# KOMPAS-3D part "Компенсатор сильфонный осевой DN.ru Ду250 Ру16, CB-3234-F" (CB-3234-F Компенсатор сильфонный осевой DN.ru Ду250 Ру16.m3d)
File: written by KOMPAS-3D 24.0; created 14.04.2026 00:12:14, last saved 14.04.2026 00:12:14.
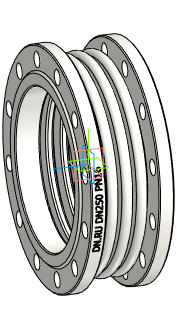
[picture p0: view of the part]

Document properties: Автор: DN.RU; Полное имя файла: D:\PROJECT CAD\DN.RU\...198(ACTUALE). CB-3234-F Компенсатор сильфонный осевой DN.ru\Исходники\DN250\CB-3234-F Компенсатор сильфонный осевой DN.ru Ду250 Ру16.m3d

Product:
- Body: Твердое тело1  | qty 1
    Масса: 34.981175
- Part/product: Компенсатор сильфонный осевой DN.ru Ду250 Ру16  | designation CB-3234-F
    Масса: 25.5
    Раздел спецификации: Прочие изделия
    Комментарий: D140-02120
    Примечание: D140-02120
    additional columns: Типовые

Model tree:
1. Твердое тело1  (labels: Твердое тело1)

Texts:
  CB-3234-F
